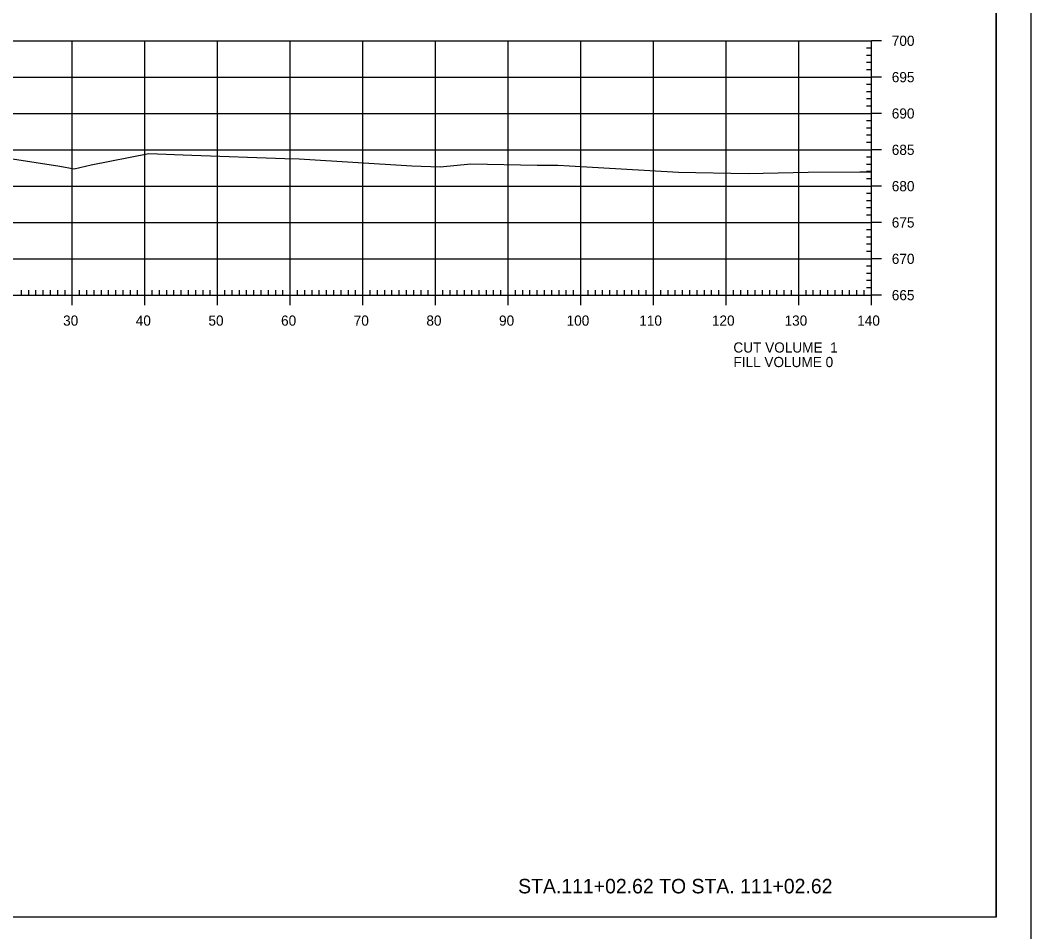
# Model space of a CAD drawing. Extents: x 1360146 to 1361431, y 631444 to 632352.
# Drawn here: x 1360340.6 to 1360479.7, y 632086.2 to 632211.6 of the extents above; entities that cross this region are included whole.
import ezdxf

# ---------------------------------------------------------------- set-up
doc = ezdxf.new("R2010")
doc.units = 0
for name, color, linetype in [('R_Axis', 7, 'Continuous'), ('R_Axis Annot', 7, 'Continuous'), ('R_Border', 7, 'Continuous'), ('R_Draft', 7, 'Continuous'), ('R_Exist Surface', 7, 'Continuous'), ('R_Grid', 7, 'Continuous'), ('R_No Plot', 7, 'Continuous')]:
    doc.layers.add(name, color=color, linetype=linetype)

msp = doc.modelspace()

# ---------------------------------------------------------------- linework, layer by layer
at = {"layer": 'R_Axis'}
for p, q in [((1360457.77, 632173.77), (1360457.77, 632208.77)), ((1360459.17, 632208.77), (1360457.77, 632208.77)), ((1360457.77, 632207.77), (1360457.07, 632207.77)), ((1360457.77, 632206.77), (1360457.07, 632206.77)), ((1360457.77, 632205.77), (1360457.07, 632205.77)), ((1360457.77, 632204.77), (1360457.07, 632204.77)), ((1360459.17, 632203.77), (1360457.77, 632203.77)), ((1360457.77, 632202.77), (1360457.07, 632202.77)), ((1360457.77, 632201.77), (1360457.07, 632201.77)), ((1360457.77, 632200.77), (1360457.07, 632200.77)), ((1360457.77, 632199.77), (1360457.07, 632199.77)), ((1360457.77, 632197.77), (1360457.07, 632197.77)), ((1360459.17, 632198.77), (1360457.77, 632198.77)), ((1360457.77, 632196.77), (1360457.07, 632196.77)), ((1360457.77, 632195.77), (1360457.07, 632195.77)), ((1360457.77, 632194.77), (1360457.07, 632194.77)), ((1360459.17, 632193.77), (1360457.77, 632193.77)), ((1360457.77, 632192.77), (1360457.07, 632192.77)), ((1360457.77, 632191.77), (1360457.07, 632191.77)), ((1360457.77, 632190.77), (1360457.07, 632190.77)), ((1360457.77, 632189.77), (1360457.07, 632189.77)), ((1360459.17, 632188.77), (1360457.77, 632188.77)), ((1360457.77, 632187.77), (1360457.07, 632187.77)), ((1360457.77, 632186.77), (1360457.07, 632186.77)), ((1360457.77, 632185.77), (1360457.07, 632185.77)), ((1360457.77, 632184.77), (1360457.07, 632184.77)), ((1360459.17, 632183.77), (1360457.77, 632183.77)), ((1360457.77, 632182.77), (1360457.07, 632182.77)), ((1360457.77, 632181.77), (1360457.07, 632181.77)), ((1360457.77, 632180.77), (1360457.07, 632180.77)), ((1360457.77, 632179.77), (1360457.07, 632179.77)), ((1360459.17, 632178.77), (1360457.77, 632178.77)), ((1360457.77, 632177.77), (1360457.07, 632177.77)), ((1360457.77, 632176.77), (1360457.07, 632176.77)), ((1360457.77, 632175.77), (1360457.07, 632175.77)), ((1360340.77, 632173.77), (1360340.77, 632174.47)), ((1360341.77, 632173.77), (1360341.77, 632174.47)), ((1360342.77, 632173.77), (1360342.77, 632174.47)), ((1360343.77, 632173.77), (1360343.77, 632174.47)), ((1360344.77, 632173.77), (1360344.77, 632174.47)), ((1360345.77, 632173.77), (1360345.77, 632174.47)), ((1360346.77, 632173.77), (1360346.77, 632174.47)), ((1360348.77, 632173.77), (1360348.77, 632174.47)), ((1360349.77, 632173.77), (1360349.77, 632174.47)), ((1360350.77, 632173.77), (1360350.77, 632174.47)), ((1360351.77, 632173.77), (1360351.77, 632174.47)), ((1360352.77, 632173.77), (1360352.77, 632174.47)), ((1360353.77, 632173.77), (1360353.77, 632174.47)), ((1360354.77, 632173.77), (1360354.77, 632174.47)), ((1360355.77, 632173.77), (1360355.77, 632174.47)), ((1360356.77, 632173.77), (1360356.77, 632174.47)), ((1360358.77, 632173.77), (1360358.77, 632174.47)), ((1360359.77, 632173.77), (1360359.77, 632174.47)), ((1360360.77, 632173.77), (1360360.77, 632174.47)), ((1360361.77, 632173.77), (1360361.77, 632174.47)), ((1360362.77, 632173.77), (1360362.77, 632174.47)), ((1360363.77, 632173.77), (1360363.77, 632174.47)), ((1360364.77, 632173.77), (1360364.77, 632174.47)), ((1360365.77, 632173.77), (1360365.77, 632174.47)), ((1360366.77, 632173.77), (1360366.77, 632174.47)), ((1360368.77, 632173.77), (1360368.77, 632174.47)), ((1360369.77, 632173.77), (1360369.77, 632174.47)), ((1360370.77, 632173.77), (1360370.77, 632174.47)), ((1360371.77, 632173.77), (1360371.77, 632174.47)), ((1360372.77, 632173.77), (1360372.77, 632174.47)), ((1360373.77, 632173.77), (1360373.77, 632174.47)), ((1360374.77, 632173.77), (1360374.77, 632174.47)), ((1360375.77, 632173.77), (1360375.77, 632174.47)), ((1360376.77, 632173.77), (1360376.77, 632174.47)), ((1360378.77, 632173.77), (1360378.77, 632174.47)), ((1360379.77, 632173.77), (1360379.77, 632174.47)), ((1360380.77, 632173.77), (1360380.77, 632174.47)), ((1360381.77, 632173.77), (1360381.77, 632174.47)), ((1360382.77, 632173.77), (1360382.77, 632174.47)), ((1360383.77, 632173.77), (1360383.77, 632174.47)), ((1360384.77, 632173.77), (1360384.77, 632174.47)), ((1360385.77, 632173.77), (1360385.77, 632174.47)), ((1360386.77, 632173.77), (1360386.77, 632174.47)), ((1360388.77, 632173.77), (1360388.77, 632174.47)), ((1360389.77, 632173.77), (1360389.77, 632174.47)), ((1360390.77, 632173.77), (1360390.77, 632174.47)), ((1360391.77, 632173.77), (1360391.77, 632174.47)), ((1360392.77, 632173.77), (1360392.77, 632174.47)), ((1360393.77, 632173.77), (1360393.77, 632174.47)), ((1360394.77, 632173.77), (1360394.77, 632174.47)), ((1360395.77, 632173.77), (1360395.77, 632174.47)), ((1360396.77, 632173.77), (1360396.77, 632174.47)), ((1360398.77, 632173.77), (1360398.77, 632174.47)), ((1360399.77, 632173.77), (1360399.77, 632174.47)), ((1360400.77, 632173.77), (1360400.77, 632174.47)), ((1360401.77, 632173.77), (1360401.77, 632174.47)), ((1360402.77, 632173.77), (1360402.77, 632174.47)), ((1360403.77, 632173.77), (1360403.77, 632174.47)), ((1360404.77, 632173.77), (1360404.77, 632174.47)), ((1360405.77, 632173.77), (1360405.77, 632174.47)), ((1360406.77, 632173.77), (1360406.77, 632174.47)), ((1360408.77, 632173.77), (1360408.77, 632174.47)), ((1360409.77, 632173.77), (1360409.77, 632174.47)), ((1360410.77, 632173.77), (1360410.77, 632174.47)), ((1360411.77, 632173.77), (1360411.77, 632174.47)), ((1360412.77, 632173.77), (1360412.77, 632174.47)), ((1360413.77, 632173.77), (1360413.77, 632174.47)), ((1360414.77, 632173.77), (1360414.77, 632174.47)), ((1360415.77, 632173.77), (1360415.77, 632174.47)), ((1360416.77, 632173.77), (1360416.77, 632174.47)), ((1360418.77, 632173.77), (1360418.77, 632174.47)), ((1360419.77, 632173.77), (1360419.77, 632174.47)), ((1360420.77, 632173.77), (1360420.77, 632174.47)), ((1360421.77, 632173.77), (1360421.77, 632174.47)), ((1360422.77, 632173.77), (1360422.77, 632174.47)), ((1360423.77, 632173.77), (1360423.77, 632174.47)), ((1360424.77, 632173.77), (1360424.77, 632174.47)), ((1360425.77, 632173.77), (1360425.77, 632174.47)), ((1360426.77, 632173.77), (1360426.77, 632174.47)), ((1360428.77, 632173.77), (1360428.77, 632174.47)), ((1360429.77, 632173.77), (1360429.77, 632174.47)), ((1360430.77, 632173.77), (1360430.77, 632174.47)), ((1360431.77, 632173.77), (1360431.77, 632174.47)), ((1360432.77, 632173.77), (1360432.77, 632174.47)), ((1360433.77, 632173.77), (1360433.77, 632174.47)), ((1360434.77, 632173.77), (1360434.77, 632174.47)), ((1360435.77, 632173.77), (1360435.77, 632174.47)), ((1360436.77, 632173.77), (1360436.77, 632174.47)), ((1360438.77, 632173.77), (1360438.77, 632174.47)), ((1360439.77, 632173.77), (1360439.77, 632174.47)), ((1360440.77, 632173.77), (1360440.77, 632174.47)), ((1360441.77, 632173.77), (1360441.77, 632174.47)), ((1360442.77, 632173.77), (1360442.77, 632174.47)), ((1360443.77, 632173.77), (1360443.77, 632174.47)), ((1360444.77, 632173.77), (1360444.77, 632174.47)), ((1360445.77, 632173.77), (1360445.77, 632174.47)), ((1360446.77, 632173.77), (1360446.77, 632174.47)), ((1360448.77, 632173.77), (1360448.77, 632174.47)), ((1360449.77, 632173.77), (1360449.77, 632174.47)), ((1360450.77, 632173.77), (1360450.77, 632174.47)), ((1360451.77, 632173.77), (1360451.77, 632174.47)), ((1360452.77, 632173.77), (1360452.77, 632174.47)), ((1360453.77, 632173.77), (1360453.77, 632174.47)), ((1360454.77, 632173.77), (1360454.77, 632174.47)), ((1360455.77, 632173.77), (1360455.77, 632174.47)), ((1360456.77, 632173.77), (1360456.77, 632174.47)), ((1360457.77, 632174.77), (1360457.07, 632174.77)), ((1360177.77, 632173.77), (1360457.77, 632173.77)), ((1360347.77, 632172.37), (1360347.77, 632173.77)), ((1360357.77, 632172.37), (1360357.77, 632173.77)), ((1360367.77, 632172.37), (1360367.77, 632173.77)), ((1360377.77, 632172.37), (1360377.77, 632173.77)), ((1360387.77, 632172.37), (1360387.77, 632173.77)), ((1360397.77, 632172.37), (1360397.77, 632173.77)), ((1360407.77, 632172.37), (1360407.77, 632173.77)), ((1360417.77, 632172.37), (1360417.77, 632173.77)), ((1360427.77, 632172.37), (1360427.77, 632173.77)), ((1360437.77, 632172.37), (1360437.77, 632173.77)), ((1360447.77, 632172.37), (1360447.77, 632173.77)), ((1360457.77, 632172.37), (1360457.77, 632173.77)), ((1360459.17, 632173.77), (1360457.77, 632173.77))]:
    msp.add_line(p, q, dxfattribs=at)
at = {"layer": 'R_Border'}
for q in [(1360474.95, 632293.62), (1360158.77, 632088.16)]:
    msp.add_line((1360474.95, 632088.16), q, dxfattribs=at)
at = {"layer": 'R_Exist Surface'}
msp.add_lwpolyline([(1360336.22, 632193.04), (1360346.04, 632191.5), (1360348.01, 632191.15), (1360350.36, 632191.72), (1360358.31, 632193.24), (1360364.22, 632193.05), (1360377.02, 632192.59), (1360379, 632192.52), (1360394.49, 632191.56), (1360398.42, 632191.45), (1360402.63, 632191.82), (1360411.74, 632191.67), (1360414.6, 632191.64), (1360416.2, 632191.56), (1360431.2, 632190.68), (1360440.81, 632190.53), (1360449.08, 632190.71), (1360456.15, 632190.74), (1360457.77, 632190.72)], dxfattribs=at)
at = {"layer": 'R_Grid'}
for p, q in [((1360177.77, 632208.77), (1360457.77, 632208.77)), ((1360347.77, 632173.77), (1360347.77, 632208.77)), ((1360357.77, 632173.77), (1360357.77, 632208.77)), ((1360367.77, 632173.77), (1360367.77, 632208.77)), ((1360377.77, 632173.77), (1360377.77, 632208.77)), ((1360387.77, 632173.77), (1360387.77, 632208.77)), ((1360397.77, 632173.77), (1360397.77, 632208.77)), ((1360407.77, 632173.77), (1360407.77, 632208.77)), ((1360417.77, 632173.77), (1360417.77, 632208.77)), ((1360427.77, 632173.77), (1360427.77, 632208.77)), ((1360437.77, 632173.77), (1360437.77, 632208.77)), ((1360447.77, 632173.77), (1360447.77, 632208.77)), ((1360457.77, 632173.77), (1360457.77, 632208.77)), ((1360177.77, 632203.77), (1360457.77, 632203.77)), ((1360177.77, 632198.77), (1360457.77, 632198.77)), ((1360177.77, 632193.77), (1360457.77, 632193.77)), ((1360177.77, 632188.77), (1360457.77, 632188.77)), ((1360177.77, 632183.77), (1360457.77, 632183.77)), ((1360177.77, 632178.77), (1360457.77, 632178.77)), ((1360177.77, 632173.77), (1360457.77, 632173.77))]:
    msp.add_line(p, q, dxfattribs=at)
at = {"layer": 'R_No Plot'}
for points in [[(1360146.36, 632297.51), (1360479.7, 632297.51), (1360479.7, 632084.17), (1360146.36, 632084.17)], [(1360392.69, 632293.62), (1360392.69, 632283.74), (1360428.42, 632283.74), (1360428.42, 632280.82), (1360451.62, 632280.82), (1360451.62, 632256.49), (1360474.95, 632256.49), (1360474.95, 632088.16), (1360158.77, 632088.16), (1360158.77, 632293.62)]]:
    msp.add_lwpolyline(points, close=True, dxfattribs=at)

# ---------------------------------------------------------------- texts
at = {"layer": 'R_Axis Annot'}
for s, p in [('700', (1360460.57, 632208.07)), ('695', (1360460.57, 632203.07)), ('690', (1360460.57, 632198.07)), ('685', (1360460.57, 632193.07)), ('680', (1360460.57, 632188.07)), ('675', (1360460.57, 632183.07)), ('670', (1360460.57, 632178.07)), ('665', (1360460.57, 632173.07)), ('30', (1360346.51, 632169.57)), ('40', (1360356.51, 632169.57)), ('50', (1360366.51, 632169.57)), ('60', (1360376.51, 632169.57)), ('70', (1360386.51, 632169.57)), ('80', (1360396.51, 632169.57)), ('90', (1360406.51, 632169.57)), ('100', (1360415.81, 632169.57)), ('110', (1360425.81, 632169.57)), ('120', (1360435.81, 632169.57)), ('130', (1360445.81, 632169.57)), ('140', (1360455.81, 632169.57)), ('CUT VOLUME  1', (1360438.77, 632165.87)), ('FILL VOLUME 0', (1360438.77, 632163.87))]:
    msp.add_text(s, height=1.4, dxfattribs=at).set_placement(p)
at = {"layer": 'R_Draft'}
msp.add_text('STA.111+02.62 TO STA. 111+02.62', height=2, dxfattribs=at).set_placement((1360409.14, 632091.45))

doc.saveas('drawing.dxf')
